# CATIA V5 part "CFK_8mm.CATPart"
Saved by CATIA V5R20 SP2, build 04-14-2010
Part number: CFK_8mm
Bounding box of the stored display mesh (mm): x -4 to 4, y -3.983 to 3.983, z 0 to 180
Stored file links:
  C:\Documents and Settings\Administrator\My Documents\Hobi_dokumenti\CAD_CNC\Clap_CATIA\CFK_8mm.CATPart
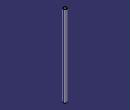
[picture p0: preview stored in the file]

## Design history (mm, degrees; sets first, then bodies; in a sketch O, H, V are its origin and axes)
Body1 (main body)
  Sketch1 on xy-plane, origin (0, 0, 0), H (1, 0, 0), V (0, 1, 0)
    circle A1 centre (0, 0) radius 3
    circle A2 centre (0, 0) radius 4
    radius A2 = 4
    radius A1 = 3
  Pad1: profile Sketch1, direction (0, 0, 1), length 180
  Chamfer1: length 0.2, angle 45, on edge [face of Pad1 from Sketch1.A2 | end face of Pad1]; edge [end face of Pad1 | face of Pad1 from Sketch1.A1]; start face of Pad1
